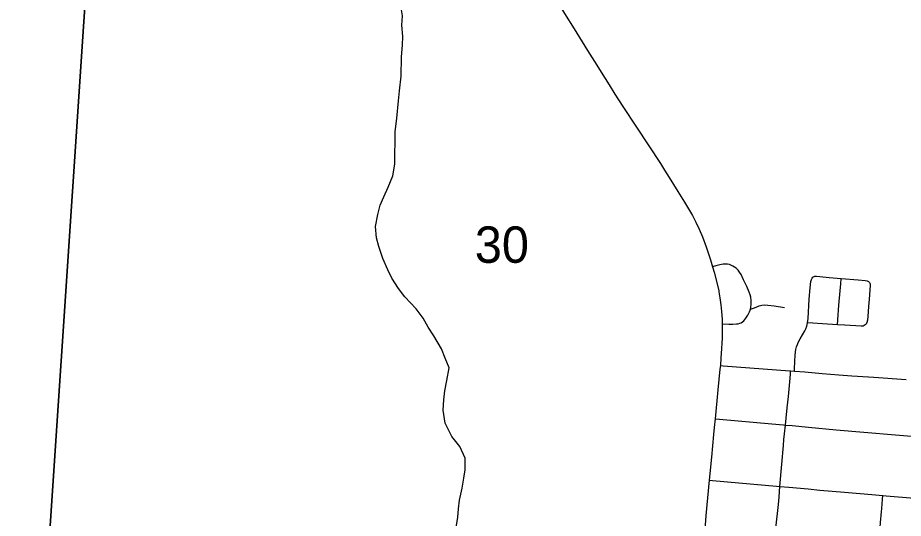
# Model space of a CAD drawing. Extents: x 0 to 1067, y 0 to 440.
# Drawn here: x 800.649 to 801.667, y 352.726 to 353.302 of the extents above; entities that cross this region are included whole.
import ezdxf

# ---------------------------------------------------------------- set-up
doc = ezdxf.new("R2010")
doc.units = 0
for name, color, linetype in [('GM_X_City_Street', 7, 'Continuous'), ('GM_X_Minor_River', 7, 'Continuous'), ('GM_X_Section', 7, 'Continuous'), ('GM_X_Section_Text', 7, 'Continuous'), ('GM_X_State_Route', 7, 'Continuous')]:
    doc.layers.add(name, color=color, linetype=linetype)

msp = doc.modelspace()

# ---------------------------------------------------------------- linework, layer by layer
at = {"layer": 'GM_X_City_Street'}
for points in [[(801.4593, 352.9497), (801.4669, 352.9495), (801.4714, 352.9494), (801.4757, 352.9496), (801.4777, 352.9497), (801.4795, 352.9503), (801.4812, 352.951), (801.4827, 352.9521), (801.484, 352.9533), (801.4863, 352.9563), (801.4886, 352.9596), (801.4908, 352.9636), (801.4914, 352.9654), (801.4916, 352.9664), (801.4921, 352.9685), (801.4924, 352.9722), (801.4924, 352.9765), (801.492, 352.9802), (801.4913, 352.9832), (801.4903, 352.9862), (801.4876, 352.9925), (801.4837, 353.0005), (801.4809, 353.0064), (801.4793, 353.009), (801.4774, 353.0115), (801.4752, 353.0136), (801.4735, 353.0149), (801.4715, 353.0161), (801.47, 353.0169), (801.4677, 353.0178), (801.4653, 353.0183), (801.4628, 353.0185), (801.4603, 353.0184), (801.4567, 353.0176), (801.4519, 353.0164), (801.448, 353.0154)], [(801.5423, 352.8953), (801.5424, 352.8971), (801.5428, 352.9073), (801.5431, 352.9131), (801.5434, 352.9176), (801.5439, 352.9202), (801.5447, 352.9234), (801.5458, 352.9261), (801.5466, 352.9282), (801.5488, 352.9326), (801.5543, 352.9416), (801.5554, 352.9439), (801.5565, 352.947), (801.5573, 352.9508), (801.5579, 352.9557), (801.5594, 352.9781), (801.5604, 352.991), (801.5613, 352.9984), (801.5618, 353.0006), (801.5626, 353.0021), (801.5636, 353.0033), (801.5648, 353.0041), (801.5658, 353.0044), (801.5675, 353.0045), (801.5714, 353.0042), (801.5823, 353.0031), (801.5961, 353.0019), (801.6157, 353.0002), (801.6237, 352.9995), (801.626, 352.999), (801.6274, 352.9983), (801.6285, 352.9973), (801.629, 352.9964), (801.6292, 352.9954), (801.6292, 352.9937), (801.6281, 352.9782), (801.6274, 352.9695), (801.6268, 352.9581), (801.6262, 352.9541), (801.6255, 352.9512), (801.6246, 352.9494), (801.6237, 352.9484), (801.6226, 352.9476), (801.6213, 352.9472), (801.619, 352.947), (801.6004, 352.9482), (801.5919, 352.9487), (801.5744, 352.9497), (801.5633, 352.9504), (801.5573, 352.9508)], [(801.5919, 352.9487), (801.5923, 352.9543), (801.5935, 352.971), (801.5948, 352.9876), (801.5955, 352.9956), (801.5961, 353.0019)], [(801.4916, 352.9664), (801.4962, 352.9682), (801.5018, 352.9704), (801.5049, 352.9711), (801.5079, 352.9714), (801.5117, 352.9713), (801.5191, 352.9704), (801.5307, 352.9685)], [(801.4571, 352.9017), (801.4605, 352.9014), (801.4911, 352.8992), (801.5371, 352.8958), (801.5379, 352.8957), (801.5423, 352.8953), (801.5544, 352.8943), (801.5742, 352.8925), (801.5934, 352.8911), (801.6082, 352.8899), (801.6149, 352.8895), (801.6335, 352.8882), (801.6707, 352.8857)], [(801.5172, 352.6814), (801.5176, 352.685), (801.5184, 352.6915), (801.5198, 352.7039), (801.5214, 352.7179), (801.5236, 352.7383), (801.5243, 352.7457), (801.5246, 352.7506), (801.5256, 352.7626), (801.5278, 352.7882), (801.5297, 352.8098), (801.5302, 352.8166), (801.5309, 352.8233), (801.532, 352.8332), (801.5329, 352.8412), (801.5341, 352.8529), (801.5353, 352.8661), (801.5368, 352.883), (801.5376, 352.8918), (801.5379, 352.8957)], [(801.451, 352.8404), (801.456, 352.8399), (801.5162, 352.8345), (801.5299, 352.8334), (801.532, 352.8332), (801.5398, 352.8326), (801.5583, 352.831), (801.5904, 352.8279), (801.6901, 352.8194), (801.7512, 352.8135), (801.7583, 352.8128)], [(801.4444, 352.7697), (801.4479, 352.7694), (801.5085, 352.764), (801.5215, 352.763), (801.5256, 352.7626), (801.5357, 352.7617), (801.5579, 352.7597), (801.5715, 352.7584), (801.5998, 352.7561), (801.6311, 352.7534), (801.6438, 352.7522), (801.6477, 352.7519), (801.6802, 352.7492)], [(801.6353, 352.6709), (801.636, 352.6779), (801.6369, 352.6856), (801.638, 352.694), (801.6398, 352.7086), (801.6407, 352.7159), (801.6412, 352.7213), (801.6424, 352.7335), (801.6426, 352.7371), (801.6434, 352.7479), (801.6438, 352.7522)]]:
    msp.add_lwpolyline(points, dxfattribs=at)
at = {"layer": 'GM_X_Minor_River'}
for points in [[(801.0919, 353.2801), (801.091, 353.2934), (801.0916, 353.304), (801.0899, 353.3154), (801.0782, 353.3183), (801.0657, 353.3208), (801.0558, 353.3217), (801.0463, 353.3219), (801.0343, 353.3262), (801.033, 353.3388), (801.032, 353.3494), (801.0319, 353.3627), (801.034, 353.376), (801.0336, 353.392)], [(801.1529, 352.7132), (801.1551, 352.7272), (801.156, 352.7367), (801.1573, 352.7469), (801.1602, 352.7606), (801.1623, 352.7723), (801.1636, 352.7818), (801.1638, 352.7951), (801.1576, 352.8085), (801.1483, 352.82), (801.1406, 352.8353), (801.1386, 352.8502), (801.1392, 352.8623), (801.1402, 352.8726), (801.1427, 352.8847), (801.1452, 352.8991), (801.1408, 352.9101), (801.1365, 352.9208), (801.1276, 352.9358), (801.121, 352.9458), (801.1154, 352.9561), (801.1073, 352.9669), (801.0942, 352.9808), (801.0872, 352.9904), (801.0794, 353.0023), (801.075, 353.0119), (801.0692, 353.0249), (801.0645, 353.0386), (801.0616, 353.0486), (801.0607, 353.0615), (801.0633, 353.0755), (801.0661, 353.0861), (801.0701, 353.0959), (801.0752, 353.1068), (801.0804, 353.12), (801.0829, 353.1333), (801.0827, 353.145), (801.0833, 353.1595), (801.0832, 353.1705), (801.0853, 353.1864), (801.0872, 353.2061), (801.0882, 353.2179), (801.0903, 353.2345), (801.0907, 353.2569), (801.0917, 353.2702), (801.0919, 353.2801)]]:
    msp.add_lwpolyline(points, dxfattribs=at)
at = {"layer": 'GM_X_Section'}
for points in [[(799.6925, 353.7106), (800.7452, 353.5961), (800.6794, 352.6083), (799.6121, 352.7044)], [(800.7452, 353.5961), (801.7432, 353.4993), (801.6612, 352.5101), (800.6794, 352.6083)]]:
    msp.add_lwpolyline(points, close=True, dxfattribs=at)
at = {"layer": 'GM_X_State_Route'}
for points in [[(801.1277, 353.5521), (801.1336, 353.5426), (801.1544, 353.5089), (801.1884, 353.4531), (801.2124, 353.4146), (801.2254, 353.3934), (801.2312, 353.3839), (801.2446, 353.3621), (801.25, 353.3533), (801.2537, 353.3473), (801.261, 353.3351), (801.2674, 353.3244), (801.2723, 353.3164), (801.278, 353.3068), (801.2891, 353.289)], [(801.2891, 353.289), (801.3045, 353.264), (801.3151, 353.2472), (801.32, 353.2393), (801.3292, 353.2245), (801.3358, 353.214), (801.3449, 353.1999), (801.3606, 353.176), (801.3883, 353.1341), (801.3929, 353.1266)], [(801.3929, 353.1266), (801.3981, 353.1182), (801.4083, 353.1019), (801.4159, 353.0898), (801.424, 353.0762), (801.425, 353.0744), (801.429, 353.0666), (801.4329, 353.0585), (801.4365, 353.0498), (801.4407, 353.0381), (801.4456, 353.0234), (801.448, 353.0154), (801.4499, 353.0091), (801.4531, 352.9972), (801.4553, 352.9875), (801.4554, 352.9867), (801.4567, 352.9796), (801.4577, 352.9717), (801.4585, 352.9638), (801.4591, 352.9552), (801.4591, 352.9543)], [(801.4591, 352.9543), (801.4592, 352.9506), (801.4593, 352.9497), (801.4592, 352.9416), (801.4591, 352.9332), (801.4579, 352.9156), (801.4576, 352.9106)], [(801.4576, 352.9106), (801.4571, 352.9017), (801.4566, 352.8977), (801.4542, 352.8736), (801.451, 352.8404), (801.45, 352.8304), (801.4492, 352.8224), (801.4469, 352.7964), (801.4444, 352.7697), (801.4406, 352.7291), (801.4388, 352.7075)]]:
    msp.add_lwpolyline(points, dxfattribs=at)

# ---------------------------------------------------------------- texts
at = {"layer": 'GM_X_Section_Text'}
msp.add_text('30', height=0.04186, rotation=0, dxfattribs=at).set_placement((801.1748, 353.0199))

doc.saveas('drawing.dxf')
